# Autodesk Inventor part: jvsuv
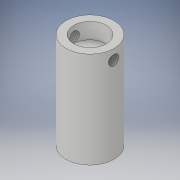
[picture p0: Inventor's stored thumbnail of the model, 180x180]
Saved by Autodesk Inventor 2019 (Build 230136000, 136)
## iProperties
Created: 2019-11
Part Number: jvsuv
Material: Generic
Document SubType Name: Sheet Metal
Designer: PRADYUMNA
Density: 1 g/cm^3
Sheet Metal Rule: Default_mm
Appearance: Default
Author: PRADYUMNA
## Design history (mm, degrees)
sketch "Sketch1"
  geometry: C1 r 7.5 at (0, 0); 1 further point
  constraints: 1 centre point, 1 coincident
  dimensions: "d0" = 15 diameter of C1
extrude "Extrusion1" new body sketch "Sketch1" distance "d1" = 30; taper "d2" = 0 deg
sketch "Sketch2"
  geometry: C1 r 5.054 at (0, 0); 1 further point
  constraints: 1 centre point, 1 coincident
extrude "Extrusion2" cut sketch "Sketch2" distance "d3" = 5; taper "d4" = 0 deg
sketch "Sketch3"
  geometry: C1 r 1.589 at (26.824, 0); 1 further point
  constraints: 1 centre point
extrude "Extrusion3" cut sketch "Sketch3" stored distance "d5" = 100; taper "d6" = 0 deg
thread "Thread1" dims "d7" = 10, "d8" = 0
thread "Thread2" dims "d9" = 10, "d10" = 0
body "Solid1"
other parameters: "Thickness" = 0.5, "BendRadius" = 0.5 (= Thickness), "BendReliefWidth" = 0.5 (= Thickness), "BendReliefDepth" = 0.25 (= 0.5 x Thickness), "CornerReliefSize" = 2 (= 4 x Thickness), "SeamGap" = 0.01, "MinimumRemnant" = 1 (= 2 x Thickness), "TransitionRadius" = 0.5 (= BendRadius), "JacobiRadiusSize" = 0.5 (= BendRadius), "GapSize" = 0.5 (= Thickness)
